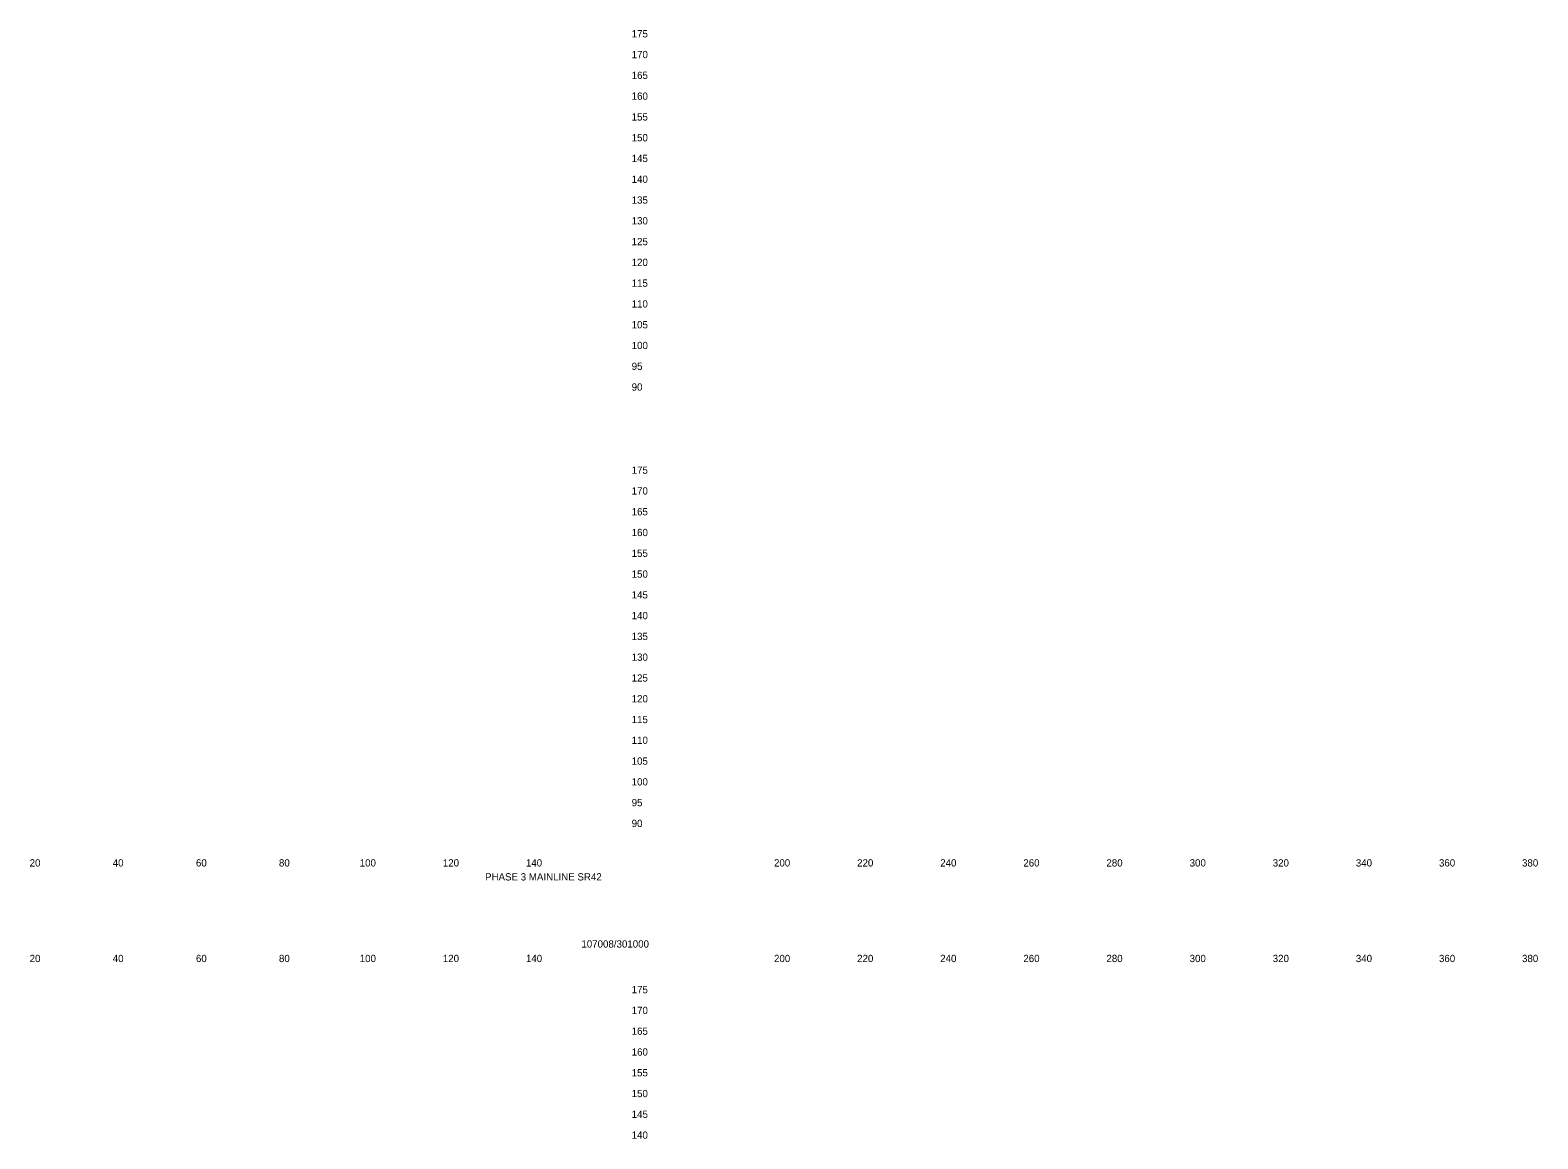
# Model space of a CAD drawing. Extents: x 21281 to 22024, y 6472 to 15198.
# Drawn here: x 21661.4 to 22024.2, y 11929.8 to 12196.6 of the extents above; entities that cross this region are included whole.
import ezdxf

# ---------------------------------------------------------------- set-up
doc = ezdxf.new("R2010")
doc.units = 0
doc.layers.add('Draft_XS_Grid', color=7, linetype='Continuous')
doc.layers.add('Draft_XS_Text', color=7, linetype='Continuous')

msp = doc.modelspace()

# ---------------------------------------------------------------- texts
at = {"layer": 'Draft_XS_Grid'}
for s, p in [('  175  ', (21804.84, 12194.84)), ('  170  ', (21804.84, 12189.84)), ('  165  ', (21804.84, 12184.84)), ('  160  ', (21804.84, 12179.84)), ('  155  ', (21804.84, 12174.84)), ('  150  ', (21804.84, 12169.84)), ('  145  ', (21804.84, 12164.84)), ('  140  ', (21804.84, 12159.84)), ('  135  ', (21804.84, 12154.84)), ('  130  ', (21804.84, 12149.84)), ('  125  ', (21804.84, 12144.84)), ('  120  ', (21804.84, 12139.84)), ('  115  ', (21804.84, 12134.84)), ('  110  ', (21804.84, 12129.84)), ('  105  ', (21804.84, 12124.84)), ('  100  ', (21804.84, 12119.84)), ('  95  ', (21804.84, 12114.84)), ('  90  ', (21804.84, 12109.84)), ('  175  ', (21804.84, 12089.84)), ('  170  ', (21804.84, 12084.84)), ('  165  ', (21804.84, 12079.84)), ('  160  ', (21804.84, 12074.84)), ('  155  ', (21804.84, 12069.84)), ('  150  ', (21804.84, 12064.84)), ('  145  ', (21804.84, 12059.84)), ('  140  ', (21804.84, 12054.84)), ('  135  ', (21804.84, 12049.84)), ('  130  ', (21804.84, 12044.84)), ('  125  ', (21804.84, 12039.84)), ('  120  ', (21804.84, 12034.84)), ('  115  ', (21804.84, 12029.84)), ('  110  ', (21804.84, 12024.84)), ('  105  ', (21804.84, 12019.84)), ('  100  ', (21804.84, 12014.84)), ('  95  ', (21804.84, 12009.84)), ('  90  ', (21804.84, 12004.84)), ('  175  ', (21804.84, 11964.84)), ('  170  ', (21804.84, 11959.84)), ('  165  ', (21804.84, 11954.84)), ('  160  ', (21804.84, 11949.84)), ('  155  ', (21804.84, 11944.84)), ('  150  ', (21804.84, 11939.84)), ('  145  ', (21804.84, 11934.84)), ('  140  ', (21804.84, 11929.84))]:
    msp.add_text(s, height=1.75, dxfattribs=at).set_placement(p)
at = {"layer": 'Draft_XS_Text'}
for s, p in [('  20  ', (21659.95, 11995.34)), ('  40  ', (21679.95, 11995.34)), ('  60  ', (21699.97, 11995.34)), ('  80  ', (21719.95, 11995.34)), ('  100  ', (21739.39, 11995.34)), ('  120  ', (21759.39, 11995.34)), ('  140  ', (21779.39, 11995.34)), ('  200  ', (21839.1, 11995.34)), ('  220  ', (21859.1, 11995.34)), ('  240  ', (21879.1, 11995.34)), ('  260  ', (21899.11, 11995.34)), ('  280  ', (21919.1, 11995.34)), ('  300  ', (21939.13, 11995.34)), ('  320  ', (21959.13, 11995.34)), ('  340  ', (21979.13, 11995.34)), ('  360  ', (21999.14, 11995.34)), ('  380  ', (22019.13, 11995.34)), ('PHASE 3 MAINLINE SR42', (21770.85, 11991.98)), ('107008/301000', (21794.04, 11975.83)), ('  20  ', (21659.95, 11972.34)), ('  40  ', (21679.95, 11972.34)), ('  60  ', (21699.97, 11972.34)), ('  80  ', (21719.95, 11972.34)), ('  100  ', (21739.39, 11972.34)), ('  120  ', (21759.39, 11972.34)), ('  140  ', (21779.39, 11972.34)), ('  200  ', (21839.1, 11972.34)), ('  220  ', (21859.1, 11972.34)), ('  240  ', (21879.1, 11972.34)), ('  260  ', (21899.11, 11972.34)), ('  280  ', (21919.1, 11972.34)), ('  300  ', (21939.13, 11972.34)), ('  320  ', (21959.13, 11972.34)), ('  340  ', (21979.13, 11972.34)), ('  360  ', (21999.14, 11972.34)), ('  380  ', (22019.13, 11972.34))]:
    msp.add_text(s, height=1.75, dxfattribs=at).set_placement(p)

doc.saveas('drawing.dxf')
